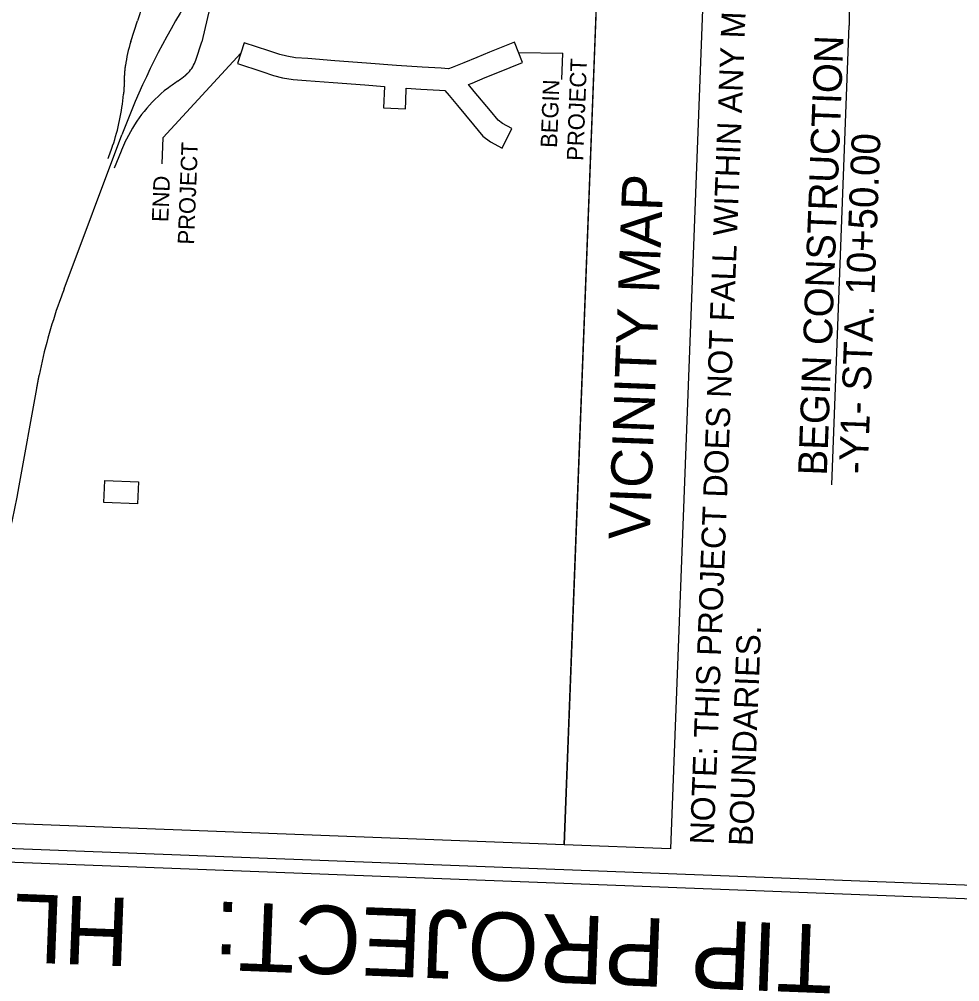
# Model space of a CAD drawing. Extents: x 2094564 to 2100382, y 679033 to 692366.
# Drawn here: x 2095618 to 2097338, y 683117 to 684877 of the extents above; entities that cross this region are included whole.
import ezdxf

# ---------------------------------------------------------------- set-up
doc = ezdxf.new("R2010")
doc.units = 0
for name, color, linetype in [('Default', 7, 'Continuous'), ('Pattern 17', 7, 'Continuous'), ('Prop Horizontal Alignment Direction Label', 7, 'Continuous'), ('Prop Shade Medium', 7, 'Continuous'), ('Scratch_Level_0', 7, 'Continuous'), ('Scratch_Level_2', 7, 'Continuous')]:
    doc.layers.add(name, color=color, linetype=linetype)

msp = doc.modelspace()

# ---------------------------------------------------------------- linework, layer by layer
at = {"layer": 'Default'}
for p, q in [((2096022.8, 684814.6), (2095881, 684660.3)), ((2096530.6, 684816.1), (2096611.5, 684814.6)), ((2096609.7, 684766.4), (2096611.5, 684814.6)), ((2095879.2, 684612.1), (2095881, 684660.3))]:
    msp.add_line(p, q, dxfattribs=at)
at = {"layer": 'Pattern 17'}
for points in [[(2094975.9, 683430.3), (2095048.9, 685332.8), (2096016.8, 685295.7), (2096009.9, 685115.7), (2096680.3, 685090), (2096614.3, 683367.4)], [(2096614.3, 683367.4), (2096687.2, 685270), (2096881.4, 685262.6), (2096808.4, 683360)]]:
    msp.add_lwpolyline(points, close=True, dxfattribs=at)
at = {"layer": 'Prop Horizontal Alignment Direction Label'}
for p, q in [((2095972.4, 684924.8), (2095951.4, 684835.4)), ((2095843.3, 684901.7), (2095834.1, 684873.9)), ((2095821.7, 684836), (2095834.1, 684873.9)), ((2095940.5, 684802), (2095951.4, 684835.4)), ((2095699.7, 684383.6), (2095805.2, 684665.3)), ((2095791.6, 684605.3), (2095804.5, 684636.1)), ((2095617.6, 684023.4), (2095649.7, 684201.6)), ((2098978.1, 683230.8), (2094806.2, 683390.8)), ((2099901.5, 683170.4), (2094805.2, 683365.8))]:
    msp.add_line(p, q, dxfattribs=at)
for centre, radius, start, end in [((2097122.1, 684172.2), 1406.2, 138.0034, 159.4705), ((2096035.5, 684765.8), 225, 161.8296, 173.2747), ((2095882.8, 684820.9), 60.7, 316.2595, 341.8296), ((2095410.1, 684773.8), 399.6, 341.2348, 355.0914), ((2096044.6, 684547.7), 255.5, 127.5503, 154.5423), ((2096549.2, 684052.4), 911.7, 160.2438, 169.0304), ((2094220.3, 684274.7), 1419.7, 322.7766, 349.8037)]:
    msp.add_arc(centre, radius, start, end, dxfattribs=at)
for points in [[(2095809.9, 684764.1), (2095809.9, 684764.5), (2095809.9, 684764.9), (2095809.9, 684765.3), (2095810, 684765.7), (2095810, 684766), (2095810, 684766.4), (2095810, 684766.8), (2095810, 684767.2), (2095810.1, 684767.5), (2095810.1, 684767.9), (2095810.1, 684768.3), (2095810.1, 684768.7), (2095810.1, 684769.1), (2095810.2, 684769.4), (2095810.2, 684769.8), (2095810.2, 684770.2), (2095810.2, 684770.6), (2095810.3, 684771), (2095810.3, 684771.3), (2095810.3, 684771.7), (2095810.3, 684772.1), (2095810.3, 684772.5), (2095810.4, 684772.9), (2095810.4, 684773.2), (2095810.4, 684773.6), (2095810.4, 684774), (2095810.5, 684774.4), (2095810.5, 684774.8), (2095810.5, 684775.1), (2095810.5, 684775.5), (2095810.6, 684775.9), (2095810.6, 684776.3), (2095810.6, 684776.7), (2095810.6, 684777), (2095810.7, 684777.4), (2095810.7, 684777.8), (2095810.7, 684778.2), (2095810.7, 684778.5), (2095810.8, 684778.9), (2095810.8, 684779.3), (2095810.8, 684779.7), (2095810.9, 684780.1), (2095810.9, 684780.4), (2095810.9, 684780.8), (2095810.9, 684781.2), (2095811, 684781.6), (2095811, 684782), (2095811, 684782.3), (2095811.1, 684782.7), (2095811.1, 684783.1), (2095811.1, 684783.5), (2095811.2, 684783.9), (2095811.2, 684784.2), (2095811.2, 684784.6), (2095811.3, 684785), (2095811.3, 684785.4), (2095811.3, 684785.7), (2095811.4, 684786.1), (2095811.4, 684786.5), (2095811.4, 684786.9), (2095811.5, 684787.3), (2095811.5, 684787.6), (2095811.5, 684788), (2095811.6, 684788.4), (2095811.6, 684788.8), (2095811.7, 684789.1), (2095811.7, 684789.5), (2095811.7, 684789.9), (2095811.8, 684790.3), (2095811.8, 684790.7), (2095811.9, 684791), (2095811.9, 684791.4), (2095812, 684791.8), (2095812, 684792.2)], [(2095907.9, 684764), (2095908.2, 684764.1), (2095908.5, 684764.3), (2095908.7, 684764.5), (2095909, 684764.7), (2095909.3, 684764.9), (2095909.5, 684765.1), (2095909.8, 684765.3), (2095910.1, 684765.4), (2095910.3, 684765.6), (2095910.6, 684765.8), (2095910.9, 684766), (2095911.1, 684766.2), (2095911.4, 684766.4), (2095911.7, 684766.6), (2095911.9, 684766.8), (2095912.2, 684766.9), (2095912.4, 684767.1), (2095912.7, 684767.3), (2095913, 684767.5), (2095913.2, 684767.7), (2095913.5, 684767.9), (2095913.8, 684768.1), (2095914, 684768.3), (2095914.3, 684768.5), (2095914.6, 684768.7), (2095914.8, 684768.8), (2095915.1, 684769), (2095915.3, 684769.2), (2095915.6, 684769.4), (2095915.9, 684769.6), (2095916.1, 684769.8), (2095916.4, 684770), (2095916.6, 684770.2), (2095916.9, 684770.4), (2095917.2, 684770.6), (2095917.4, 684770.8), (2095917.7, 684771), (2095917.9, 684771.2), (2095918.2, 684771.4), (2095918.4, 684771.6), (2095918.7, 684771.8), (2095918.9, 684772), (2095919.2, 684772.2), (2095919.4, 684772.4), (2095919.7, 684772.6), (2095920, 684772.8), (2095920.2, 684773), (2095920.5, 684773.2), (2095920.7, 684773.4), (2095921, 684773.6), (2095921.2, 684773.9), (2095921.4, 684774.1), (2095921.7, 684774.3), (2095921.9, 684774.5), (2095922.2, 684774.7), (2095922.4, 684774.9), (2095922.7, 684775.1), (2095922.9, 684775.3), (2095923.2, 684775.6), (2095923.4, 684775.8), (2095923.6, 684776), (2095923.9, 684776.2), (2095924.1, 684776.4), (2095924.3, 684776.7), (2095924.6, 684776.9), (2095924.8, 684777.1), (2095925, 684777.3), (2095925.3, 684777.6), (2095925.5, 684777.8), (2095925.7, 684778), (2095926, 684778.3), (2095926.2, 684778.5), (2095926.4, 684778.7), (2095926.7, 684779)], [(2095809.9, 684764.1), (2095809.9, 684763.8), (2095809.8, 684763.5), (2095809.8, 684763.1), (2095809.8, 684762.8), (2095809.8, 684762.5), (2095809.8, 684762.1), (2095809.7, 684761.8), (2095809.7, 684761.5), (2095809.7, 684761.1), (2095809.7, 684760.8), (2095809.7, 684760.5), (2095809.7, 684760.1), (2095809.6, 684759.8), (2095809.6, 684759.5), (2095809.6, 684759.2), (2095809.6, 684758.8), (2095809.6, 684758.5), (2095809.5, 684758.2), (2095809.5, 684757.8), (2095809.5, 684757.5), (2095809.5, 684757.2), (2095809.5, 684756.8), (2095809.4, 684756.5), (2095809.4, 684756.2), (2095809.4, 684755.8), (2095809.4, 684755.5), (2095809.4, 684755.2), (2095809.3, 684754.8), (2095809.3, 684754.5), (2095809.3, 684754.2), (2095809.3, 684753.8), (2095809.3, 684753.5), (2095809.2, 684753.2), (2095809.2, 684752.8), (2095809.2, 684752.5), (2095809.2, 684752.2), (2095809.2, 684751.8), (2095809.1, 684751.5), (2095809.1, 684751.2), (2095809.1, 684750.9), (2095809.1, 684750.5), (2095809.1, 684750.2), (2095809, 684749.9), (2095809, 684749.5), (2095809, 684749.2), (2095809, 684748.9), (2095809, 684748.5), (2095808.9, 684748.2), (2095808.9, 684747.9), (2095808.9, 684747.5), (2095808.9, 684747.2), (2095808.8, 684746.9), (2095808.8, 684746.5), (2095808.8, 684746.2), (2095808.8, 684745.9), (2095808.7, 684745.5), (2095808.7, 684745.2), (2095808.7, 684744.9), (2095808.7, 684744.5), (2095808.6, 684744.2), (2095808.6, 684743.9), (2095808.6, 684743.6), (2095808.6, 684743.2), (2095808.5, 684742.9), (2095808.5, 684742.6), (2095808.5, 684742.2), (2095808.5, 684741.9), (2095808.4, 684741.6), (2095808.4, 684741.2), (2095808.4, 684740.9), (2095808.4, 684740.6), (2095808.3, 684740.2), (2095808.3, 684739.9), (2095808.3, 684739.6)], [(2095907.9, 684764), (2095907.7, 684763.8), (2095907.4, 684763.6), (2095907.2, 684763.4), (2095906.9, 684763.2), (2095906.6, 684763.1), (2095906.4, 684762.9), (2095906.1, 684762.7), (2095905.9, 684762.5), (2095905.6, 684762.3), (2095905.3, 684762.1), (2095905.1, 684762), (2095904.8, 684761.8), (2095904.6, 684761.6), (2095904.3, 684761.4), (2095904, 684761.2), (2095903.8, 684761.1), (2095903.5, 684760.9), (2095903.3, 684760.7), (2095903, 684760.5), (2095902.7, 684760.3), (2095902.5, 684760.1), (2095902.2, 684760), (2095902, 684759.8), (2095901.7, 684759.6), (2095901.4, 684759.4), (2095901.2, 684759.2), (2095900.9, 684759.1), (2095900.7, 684758.9), (2095900.4, 684758.7), (2095900.2, 684758.5), (2095899.9, 684758.3), (2095899.6, 684758.1), (2095899.4, 684758), (2095899.1, 684757.8), (2095898.9, 684757.6), (2095898.6, 684757.4), (2095898.4, 684757.2), (2095898.1, 684757), (2095897.8, 684756.8), (2095897.6, 684756.7), (2095897.3, 684756.5), (2095897.1, 684756.3), (2095896.8, 684756.1), (2095896.6, 684755.9), (2095896.3, 684755.7), (2095896, 684755.5), (2095895.8, 684755.4), (2095895.5, 684755.2), (2095895.3, 684755), (2095895, 684754.8), (2095894.8, 684754.6), (2095894.5, 684754.4), (2095894.2, 684754.2), (2095894, 684754.1), (2095893.7, 684753.9), (2095893.5, 684753.7), (2095893.2, 684753.5), (2095893, 684753.3), (2095892.7, 684753.1), (2095892.5, 684752.9), (2095892.2, 684752.7), (2095892, 684752.5), (2095891.7, 684752.4), (2095891.4, 684752.2), (2095891.2, 684752), (2095890.9, 684751.8), (2095890.7, 684751.6), (2095890.4, 684751.4), (2095890.2, 684751.2), (2095889.9, 684751), (2095889.7, 684750.8), (2095889.4, 684750.6), (2095889.2, 684750.4), (2095888.9, 684750.3)], [(2095804.5, 684636.1), (2095804.7, 684636.4), (2095804.8, 684636.6), (2095804.9, 684636.9), (2095805, 684637.2), (2095805.2, 684637.5), (2095805.3, 684637.8), (2095805.4, 684638.1), (2095805.5, 684638.4), (2095805.6, 684638.7), (2095805.8, 684639), (2095805.9, 684639.3), (2095806, 684639.6), (2095806.1, 684639.9), (2095806.3, 684640.2), (2095806.4, 684640.4), (2095806.5, 684640.7), (2095806.6, 684641), (2095806.8, 684641.3), (2095806.9, 684641.6), (2095807, 684641.9), (2095807.1, 684642.2), (2095807.3, 684642.5), (2095807.4, 684642.8), (2095807.5, 684643.1), (2095807.6, 684643.4), (2095807.7, 684643.6), (2095807.9, 684643.9), (2095808, 684644.2), (2095808.1, 684644.5), (2095808.2, 684644.8), (2095808.4, 684645.1), (2095808.5, 684645.4), (2095808.6, 684645.7), (2095808.7, 684646), (2095808.9, 684646.3), (2095809, 684646.6), (2095809.1, 684646.8), (2095809.3, 684647.1), (2095809.4, 684647.4), (2095809.5, 684647.7), (2095809.6, 684648), (2095809.8, 684648.3), (2095809.9, 684648.6), (2095810, 684648.9), (2095810.1, 684649.2), (2095810.3, 684649.5), (2095810.4, 684649.7), (2095810.5, 684650), (2095810.7, 684650.3), (2095810.8, 684650.6), (2095810.9, 684650.9), (2095811, 684651.2), (2095811.2, 684651.5), (2095811.3, 684651.8), (2095811.4, 684652.1), (2095811.6, 684652.4), (2095811.7, 684652.6), (2095811.8, 684652.9), (2095812, 684653.2), (2095812.1, 684653.5), (2095812.2, 684653.8), (2095812.4, 684654.1), (2095812.5, 684654.4), (2095812.6, 684654.7), (2095812.7, 684654.9), (2095812.9, 684655.2), (2095813, 684655.5), (2095813.1, 684655.8), (2095813.3, 684656.1), (2095813.4, 684656.4), (2095813.6, 684656.7), (2095813.7, 684657), (2095813.8, 684657.2), (2095814, 684657.5)], [(2095780.1, 684622.1), (2095780.2, 684622.4), (2095780.3, 684622.7), (2095780.5, 684623), (2095780.6, 684623.3), (2095780.7, 684623.6), (2095780.8, 684624), (2095780.9, 684624.3), (2095781, 684624.6), (2095781.2, 684624.9), (2095781.3, 684625.2), (2095781.4, 684625.5), (2095781.5, 684625.8), (2095781.6, 684626.1), (2095781.7, 684626.4), (2095781.8, 684626.8), (2095782, 684627.1), (2095782.1, 684627.4), (2095782.2, 684627.7), (2095782.3, 684628), (2095782.4, 684628.3), (2095782.5, 684628.6), (2095782.7, 684628.9), (2095782.8, 684629.3), (2095782.9, 684629.6), (2095783, 684629.9), (2095783.1, 684630.2), (2095783.2, 684630.5), (2095783.4, 684630.8), (2095783.5, 684631.1), (2095783.6, 684631.4), (2095783.7, 684631.7), (2095783.8, 684632.1), (2095783.9, 684632.4), (2095784, 684632.7), (2095784.2, 684633), (2095784.3, 684633.3), (2095784.4, 684633.6), (2095784.5, 684633.9), (2095784.6, 684634.2), (2095784.7, 684634.6), (2095784.8, 684634.9), (2095785, 684635.2), (2095785.1, 684635.5), (2095785.2, 684635.8), (2095785.3, 684636.1), (2095785.4, 684636.4), (2095785.5, 684636.7), (2095785.6, 684637.1), (2095785.7, 684637.4), (2095785.9, 684637.7), (2095786, 684638), (2095786.1, 684638.3), (2095786.2, 684638.6), (2095786.3, 684638.9), (2095786.4, 684639.3), (2095786.5, 684639.6), (2095786.6, 684639.9), (2095786.8, 684640.2), (2095786.9, 684640.5), (2095787, 684640.8), (2095787.1, 684641.1), (2095787.2, 684641.4), (2095787.3, 684641.8), (2095787.4, 684642.1), (2095787.5, 684642.4), (2095787.6, 684642.7), (2095787.7, 684643), (2095787.8, 684643.3), (2095788, 684643.6), (2095788.1, 684644), (2095788.2, 684644.3), (2095788.3, 684644.6), (2095788.4, 684644.9), (2095788.5, 684645.2)], [(2095699.7, 684383.6), (2095699.6, 684383.3), (2095699.5, 684383), (2095699.3, 684382.7), (2095699.2, 684382.4), (2095699.1, 684382.1), (2095699, 684381.8), (2095698.9, 684381.4), (2095698.8, 684381.1), (2095698.6, 684380.8), (2095698.5, 684380.5), (2095698.4, 684380.2), (2095698.3, 684379.9), (2095698.2, 684379.6), (2095698.1, 684379.3), (2095697.9, 684378.9), (2095697.8, 684378.6), (2095697.7, 684378.3), (2095697.6, 684378), (2095697.5, 684377.7), (2095697.4, 684377.4), (2095697.2, 684377.1), (2095697.1, 684376.8), (2095697, 684376.5), (2095696.9, 684376.1), (2095696.8, 684375.8), (2095696.7, 684375.5), (2095696.5, 684375.2), (2095696.4, 684374.9), (2095696.3, 684374.6), (2095696.2, 684374.3), (2095696.1, 684374), (2095696, 684373.7), (2095695.8, 684373.3), (2095695.7, 684373), (2095695.6, 684372.7), (2095695.5, 684372.4), (2095695.4, 684372.1), (2095695.3, 684371.8), (2095695.2, 684371.5), (2095695, 684371.2), (2095694.9, 684370.8), (2095694.8, 684370.5), (2095694.7, 684370.2), (2095694.6, 684369.9), (2095694.5, 684369.6), (2095694.3, 684369.3), (2095694.2, 684369), (2095694.1, 684368.7), (2095694, 684368.3), (2095693.9, 684368), (2095693.8, 684367.7), (2095693.7, 684367.4), (2095693.5, 684367.1), (2095693.4, 684366.8), (2095693.3, 684366.5), (2095693.2, 684366.2), (2095693.1, 684365.9), (2095693, 684365.5), (2095692.9, 684365.2), (2095692.7, 684364.9), (2095692.6, 684364.6), (2095692.5, 684364.3), (2095692.4, 684364), (2095692.3, 684363.7), (2095692.2, 684363.4), (2095692.1, 684363), (2095692, 684362.7), (2095691.8, 684362.4), (2095691.7, 684362.1), (2095691.6, 684361.8), (2095691.5, 684361.5), (2095691.4, 684361.2), (2095691.3, 684360.8), (2095691.2, 684360.5)], [(2095649.7, 684201.6), (2095649.8, 684202), (2095649.8, 684202.3), (2095649.9, 684202.6), (2095649.9, 684203), (2095650, 684203.3), (2095650, 684203.6), (2095650.1, 684203.9), (2095650.2, 684204.3), (2095650.2, 684204.6), (2095650.3, 684204.9), (2095650.3, 684205.2), (2095650.4, 684205.6), (2095650.5, 684205.9), (2095650.5, 684206.2), (2095650.6, 684206.6), (2095650.6, 684206.9), (2095650.7, 684207.2), (2095650.8, 684207.5), (2095650.8, 684207.9), (2095650.9, 684208.2), (2095650.9, 684208.5), (2095651, 684208.8), (2095651, 684209.2), (2095651.1, 684209.5), (2095651.2, 684209.8), (2095651.2, 684210.2), (2095651.3, 684210.5), (2095651.3, 684210.8), (2095651.4, 684211.1), (2095651.5, 684211.5), (2095651.5, 684211.8), (2095651.6, 684212.1), (2095651.6, 684212.4), (2095651.7, 684212.8), (2095651.8, 684213.1), (2095651.8, 684213.4), (2095651.9, 684213.8), (2095651.9, 684214.1), (2095652, 684214.4), (2095652.1, 684214.7), (2095652.1, 684215.1), (2095652.2, 684215.4), (2095652.2, 684215.7), (2095652.3, 684216), (2095652.4, 684216.4), (2095652.4, 684216.7), (2095652.5, 684217), (2095652.5, 684217.4), (2095652.6, 684217.7), (2095652.7, 684218), (2095652.7, 684218.3), (2095652.8, 684218.7), (2095652.9, 684219), (2095652.9, 684219.3), (2095653, 684219.6), (2095653, 684220), (2095653.1, 684220.3), (2095653.2, 684220.6), (2095653.2, 684220.9), (2095653.3, 684221.3), (2095653.3, 684221.6), (2095653.4, 684221.9), (2095653.5, 684222.3), (2095653.5, 684222.6), (2095653.6, 684222.9), (2095653.7, 684223.2), (2095653.7, 684223.6), (2095653.8, 684223.9), (2095653.8, 684224.2), (2095653.9, 684224.5), (2095654, 684224.9), (2095654, 684225.2), (2095654.1, 684225.5), (2095654.2, 684225.8)]]:
    msp.add_spline(points, degree=3, dxfattribs=at)
at = {"layer": 'Prop Shade Medium'}
for p, q in [((2096028.9, 684833.7), (2096016.7, 684795.6)), ((2096538.1, 684797.6), (2096523.1, 684834.7)), ((2096285.5, 684753.8), (2096283.8, 684714.5)), ((2096283.8, 684714.5), (2096323.8, 684712.9)), ((2096500.6, 684641.2), (2096518.7, 684676.9))]:
    msp.add_line(p, q, dxfattribs=at)
for points in [[(2096307.4, 684792.2), (2096252.7, 684796.5), (2096194.9, 684800.8), (2096145.6, 684804.7), (2096123, 684806.5), (2096106.7, 684809), (2096094, 684812.2), (2096073.8, 684819.3), (2096028.9, 684833.7)], [(2096523.1, 684834.7), (2096477.9, 684816.6), (2096454.2, 684807), (2096430.7, 684797.1), (2096409.5, 684788.3), (2096402.4, 684785.9)], [(2096016.7, 684795.6), (2096061, 684781.4), (2096082.5, 684773.8), (2096098.8, 684769.8), (2096118.3, 684766.7), (2096142.5, 684764.8), (2096191.9, 684760.9), (2096249.7, 684756.6), (2096285.5, 684753.8)], [(2096402.4, 684785.9), (2096389.2, 684787.1), (2096354.7, 684788.9), (2096307.4, 684792.2)], [(2096439.2, 684757.3), (2096446.1, 684760.1), (2096469.6, 684770), (2096492.8, 684779.5), (2096538.1, 684797.6)], [(2096518.7, 684676.9), (2096501.2, 684686.2), (2096493.3, 684692.1), (2096479.3, 684709.2), (2096449.7, 684744.6), (2096439.2, 684757.3)], [(2096323.8, 684712.9), (2096324.4, 684726.9), (2096325.3, 684750.9)], [(2096325.3, 684750.9), (2096352.2, 684749), (2096386.4, 684747.2), (2096395.8, 684746.4)], [(2096395.8, 684746.4), (2096403.8, 684737.3), (2096418.9, 684719), (2096448.5, 684683.6), (2096465.4, 684663.2), (2096479.5, 684652.4), (2096500.6, 684641.2)]]:
    msp.add_lwpolyline(points, dxfattribs=at)
at = {"layer": 'Scratch_Level_0'}
for p in [(2097143.6, 685552.6), (2097103.5, 684025.4)]:
    msp.add_line(p, (2097135.7, 684865.5), dxfattribs=at)
at = {"layer": 'Scratch_Level_2'}
msp.add_lwpolyline([(2095772.5, 683993.2), (2095774.1, 684033.7), (2095835.5, 684031.3), (2095833.9, 683990.8)], close=True, dxfattribs=at)

# ---------------------------------------------------------------- texts
at = {"layer": 'Default'}
for s, p in [('PROJECT', (2096648.9, 684617.5)), ('BEGIN', (2096601, 684641.2)), ('PROJECT', (2095937.3, 684464.3)), ('END', (2095890.1, 684505.5))]:
    msp.add_text(s, height=30, rotation=87.8037, dxfattribs=at).set_placement(p)
at = {"layer": 'Prop Horizontal Alignment Direction Label'}
for s, height, rotation, p in [('VICINITY MAP', 75, 87.8037, (2096770.3, 683923.8)), ('HL-0008I', 125, 177.8037, (2095822.1, 683269.9)), ('TIP PROJECT:', 125, 177.8037, (2097108.2, 683220.5))]:
    msp.add_text(s, height=height, rotation=rotation, dxfattribs=at).set_placement(p)
at = {"layer": 'Scratch_Level_0'}
for s, height, p in [('NOTE: THIS PROJECT DOES NOT FALL WITHIN ANY MUNICIPAL', 43.826, (2096887.7, 683367.2)), ('BEGIN CONSTRUCTION', 52.591, (2097094.4, 684041.9)), ('-Y1- STA. 10+50.00', 52.591, (2097169, 684044.4)), ('BOUNDARIES.', 43.826, (2096958.8, 683364.5))]:
    msp.add_text(s, height=height, rotation=87.8037, dxfattribs=at).set_placement(p)

doc.saveas('drawing.dxf')
